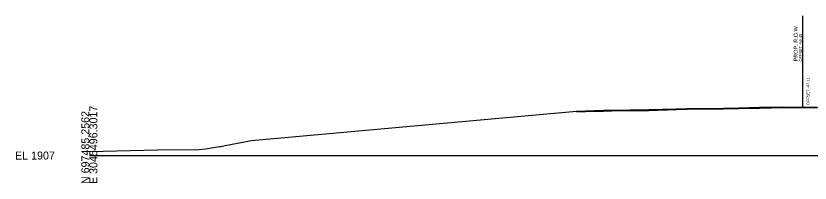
# Model space of a CAD drawing. Extents: x 1574 to 14903, y 7971 to 16537.
# Drawn here: x 14274.3 to 14552.1, y 8990.3 to 9049 of the extents above; entities that cross this region are included whole.
import ezdxf

# ---------------------------------------------------------------- set-up
doc = ezdxf.new("R2010")
doc.units = 0
for name, color, linetype in [('DESIGN - ROW - Right-of-Way and Easement Labels', 7, 'Continuous'), ('DESIGN - ROW - Right-of-Way Linework', 7, 'Continuous'), ('DESIGN - SHEET - Light Grid', 7, 'Continuous'), ('DESIGN - TYPICAL - Slope Tie Text', 7, 'Continuous'), ('SURVEY - GROUND - Bottom of Topsoil Layer', 7, 'Continuous'), ('SURVEY - GROUND - Top of Ground', 7, 'Continuous')]:
    doc.layers.add(name, color=color, linetype=linetype)

msp = doc.modelspace()

# ---------------------------------------------------------------- linework, layer by layer
at = {"layer": 'DESIGN - ROW - Right-of-Way Linework'}
msp.add_line((14549.55, 9016.99), (14549.55, 9048.99), dxfattribs=at)
at = {"layer": 'DESIGN - SHEET - Light Grid'}
msp.add_line((14300, 9000), (14600, 9000), dxfattribs=at)
at = {"layer": 'SURVEY - GROUND - Bottom of Topsoil Layer'}
msp.add_lwpolyline([(14470.47, 9015.31), (14473.53, 9015.42), (14479.87, 9015.6), (14482.61, 9015.65), (14495.67, 9015.84), (14505.27, 9016.13), (14509.09, 9016.22), (14521.8, 9016.33), (14527.09, 9016.5), (14534.48, 9016.66), (14542.86, 9016.82), (14554.67, 9016.68)], dxfattribs=at)
at = {"layer": 'SURVEY - GROUND - Top of Ground'}
msp.add_line((14356.76, 9005.23), (14470.46, 9015.56), dxfattribs=at)
msp.add_line((14356.76, 9005.23), (14470.46, 9015.56), dxfattribs=at)
for points in [[(14470.46, 9015.56), (14473.52, 9015.67), (14479.87, 9015.85), (14482.61, 9015.9), (14495.67, 9016.09), (14505.27, 9016.38), (14509.08, 9016.47), (14521.79, 9016.58), (14527.08, 9016.75), (14534.48, 9016.91), (14542.86, 9017.07), (14554.67, 9016.93)], [(14470.46, 9015.56), (14473.52, 9015.67), (14479.87, 9015.85), (14482.61, 9015.9), (14495.67, 9016.09), (14505.27, 9016.38), (14509.08, 9016.47), (14521.79, 9016.58), (14527.08, 9016.75), (14534.48, 9016.91), (14542.86, 9017.07), (14554.67, 9016.93)], [(14300, 9001.42), (14319.1, 9001.84), (14323.82, 9001.96), (14338.44, 9002.12), (14340.62, 9002.31), (14345.49, 9003.13), (14345.96, 9003.2), (14347.53, 9003.48), (14356.76, 9005.23)], [(14300, 9001.42), (14319.1, 9001.84), (14323.82, 9001.96), (14338.44, 9002.12), (14340.62, 9002.31), (14345.49, 9003.13), (14345.96, 9003.2), (14347.53, 9003.48), (14356.76, 9005.23)]]:
    msp.add_lwpolyline(points, dxfattribs=at)

# ---------------------------------------------------------------- texts
at = {"layer": 'DESIGN - ROW - Right-of-Way and Easement Labels'}
for s, height, p in [('PROP. R.O.W.', 1.4, (14547.8, 9032.99)), ('OFFSET -50.45', 1, (14549.3, 9032.99))]:
    msp.add_text(s, height=height, rotation=90, dxfattribs=at).set_placement(p)
at = {"layer": 'DESIGN - SHEET - Light Grid'}
for s, p in [('N 697485.2562', (14300, 8990)), ('E 3045496.3017', (14302.8, 8990))]:
    msp.add_text(s, height=2.8, rotation=90, dxfattribs=at).set_placement(p)
msp.add_text('EL 1907', height=2.8, dxfattribs=at).set_placement((14274, 8998.6))
at = {"layer": 'DESIGN - TYPICAL - Slope Tie Text'}
msp.add_text('OFFSET -47.11', height=1, rotation=90, dxfattribs=at).set_placement((14551.89, 9017.7))

doc.saveas('drawing.dxf')
